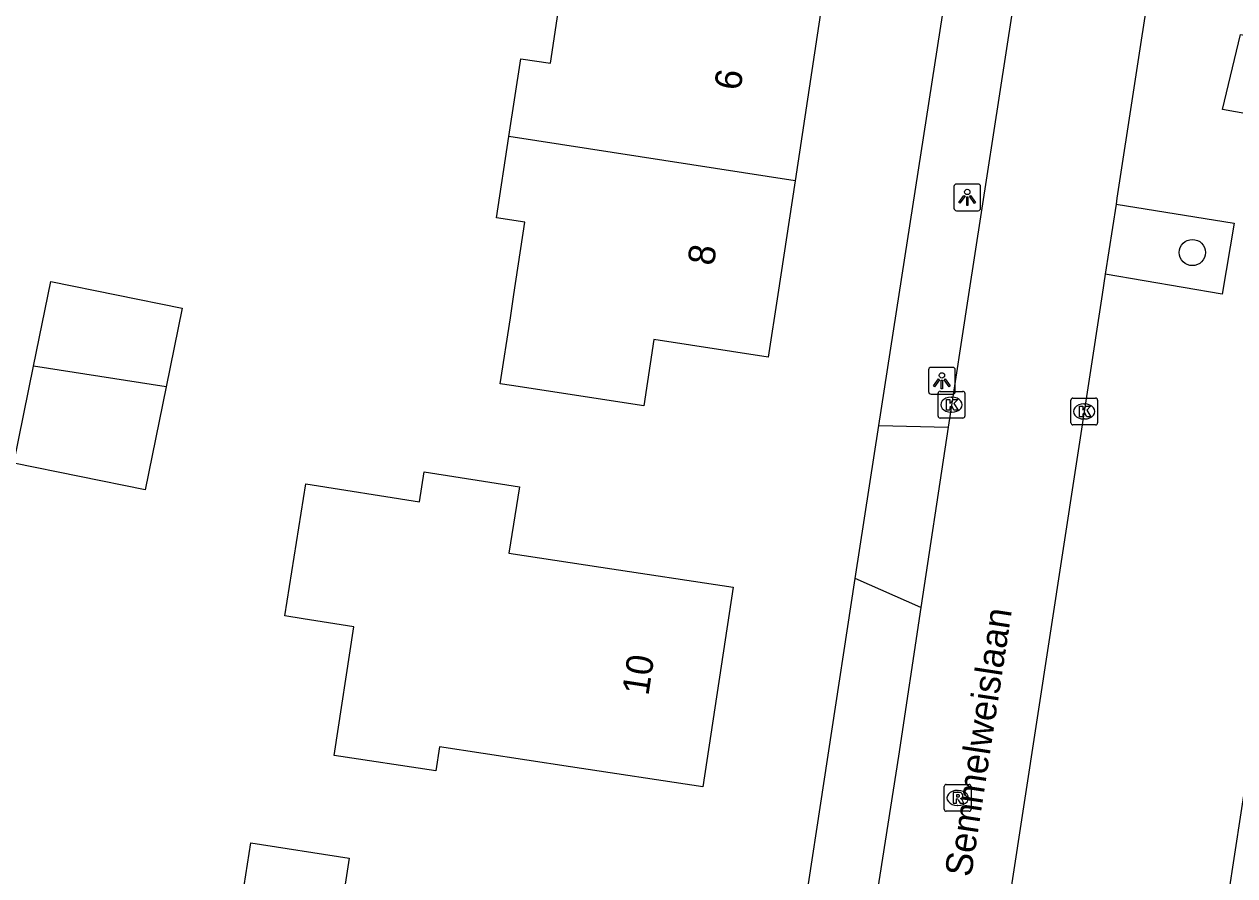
# Model space of a CAD drawing. Extents: x 161486 to 162249, y 379484 to 380829.
# Drawn here: x 161700.97 to 161746.18, y 380478.3 to 380510.09 of the extents above; entities that cross this region are included whole.
import ezdxf

# ---------------------------------------------------------------- set-up
doc = ezdxf.new("R2010")
doc.units = 0
for name, color, linetype in [('IMGEO_Boom', 7, 'Continuous'), ('IMGEO_Groenvoorziening', 7, 'Continuous'), ('IMGEO_Kolk', 7, 'Continuous'), ('IMGEO_Lichtpunt', 7, 'Continuous'), ('IMGEO_Openbare_ruimte_label', 7, 'Continuous'), ('IMGEO_Pand', 7, 'Continuous'), ('IMGEO_Pand_nummerreeks', 7, 'Continuous'), ('IMGEO_Rijbaan_lokaal_open', 7, 'Continuous'), ('IMGEO_Rioolput', 7, 'Continuous'), ('IMGEO_Voetpad_open', 7, 'Continuous')]:
    doc.layers.add(name, color=color, linetype=linetype)

msp = doc.modelspace()

# ---------------------------------------------------------------- linework, layer by layer
at = {"layer": 'IMGEO_Boom'}
msp.add_circle((161744.593, 380501.567), 0.489, dxfattribs=at)
at = {"layer": 'IMGEO_Groenvoorziening'}
for points in [[(161750.302, 380506.085), (161745.718, 380506.902), (161746.396, 380509.701), (161750.755, 380509.012)], [(161741.742, 380503.373), (161746.159, 380502.657), (161745.704, 380500.01), (161741.342, 380500.764)]]:
    msp.add_lwpolyline(points, dxfattribs=at)
at = {"layer": 'IMGEO_Kolk'}
for p, q in [((161735.097, 380495.458), (161735.097, 380496.31)), ((161735.172, 380496.384), (161736.024, 380496.384)), ((161735.585, 380496.164), (161735.61, 380496.164)), ((161736.098, 380496.31), (161736.098, 380495.458)), ((161740.055, 380495.206), (161740.055, 380496.058)), ((161740.13, 380496.132), (161740.982, 380496.132)), ((161741.056, 380496.058), (161741.056, 380495.206)), ((161735.608, 380495.604), (161735.583, 380495.604)), ((161740.543, 380495.912), (161740.568, 380495.912)), ((161736.024, 380495.384), (161735.172, 380495.384)), ((161740.982, 380495.132), (161740.13, 380495.132)), ((161740.566, 380495.352), (161740.541, 380495.352))]:
    msp.add_line(p, q, dxfattribs=at)
for points in [[(161735.097, 380495.458), (161735.097, 380496.31)], [(161735.172, 380496.384), (161736.024, 380496.384)], [(161735.418, 380496.084), (161735.541, 380496.084), (161735.541, 380495.933), (161735.671, 380496.084), (161735.835, 380496.084), (161735.689, 380495.933), (161735.842, 380495.684), (161735.69, 380495.684), (161735.605, 380495.848), (161735.541, 380495.781), (161735.541, 380495.684), (161735.418, 380495.684), (161735.418, 380496.084)], [(161736.098, 380496.31), (161736.098, 380495.458)], [(161740.055, 380495.206), (161740.055, 380496.058)], [(161740.13, 380496.132), (161740.982, 380496.132)], [(161741.056, 380496.058), (161741.056, 380495.206)], [(161740.376, 380495.832), (161740.499, 380495.832), (161740.499, 380495.681), (161740.629, 380495.832), (161740.793, 380495.832), (161740.647, 380495.681), (161740.8, 380495.432), (161740.648, 380495.432), (161740.563, 380495.596), (161740.499, 380495.529), (161740.499, 380495.432), (161740.376, 380495.432), (161740.376, 380495.832)], [(161736.024, 380495.384), (161735.172, 380495.384)], [(161740.982, 380495.132), (161740.13, 380495.132)]]:
    msp.add_lwpolyline(points, dxfattribs=at)
for centre, start, end in [((161735.174, 380496.308), 91.552, 178.448), ((161735.174, 380496.308), 91.552, 178.448), ((161736.022, 380496.308), 1.552, 88.448), ((161736.022, 380496.308), 1.552, 88.448), ((161740.132, 380496.056), 91.552, 178.448), ((161740.132, 380496.056), 91.552, 178.448), ((161740.98, 380496.056), 1.552, 88.448), ((161740.98, 380496.056), 1.552, 88.448), ((161735.174, 380495.46), 181.552, 268.448), ((161735.174, 380495.46), 181.552, 268.448), ((161736.022, 380495.46), 271.552, 358.448), ((161736.022, 380495.46), 271.552, 358.448), ((161740.132, 380495.208), 181.552, 268.448), ((161740.132, 380495.208), 181.552, 268.448), ((161740.98, 380495.208), 271.552, 358.448), ((161740.98, 380495.208), 271.552, 358.448)]:
    msp.add_arc(centre, 0.0765, start, end, dxfattribs=at)
for centre, major_axis, ratio, start_param, end_param in [((161735.584, 380495.884), (-0.387, 0.002), 0.722429, 4.712389, 7.853982), ((161735.609, 380495.884), (-0.39, 0.002), 0.717154, 1.570796, 4.712389), ((161740.542, 380495.632), (-0.387, 0.002), 0.722429, 4.712389, 7.853982), ((161740.567, 380495.632), (-0.39, 0.002), 0.717154, 1.570796, 4.712389)]:
    msp.add_ellipse(centre, major_axis=major_axis, ratio=ratio, start_param=start_param, end_param=end_param, dxfattribs=at)
at = {"layer": 'IMGEO_Lichtpunt'}
for p, q in [((161735.69, 380504.029), (161735.69, 380503.222)), ((161735.69, 380504.029), (161735.69, 380503.222)), ((161736.592, 380504.124), (161735.784, 380504.124)), ((161736.592, 380504.124), (161735.784, 380504.124)), ((161736.686, 380503.222), (161736.686, 380504.029)), ((161736.686, 380503.222), (161736.686, 380504.029)), ((161735.784, 380503.128), (161736.592, 380503.128)), ((161735.784, 380503.128), (161736.592, 380503.128)), ((161734.741, 380497.183), (161734.741, 380496.376)), ((161734.741, 380497.183), (161734.741, 380496.376)), ((161735.643, 380497.278), (161734.835, 380497.278)), ((161735.643, 380497.278), (161734.835, 380497.278)), ((161735.737, 380496.376), (161735.737, 380497.183)), ((161735.737, 380496.376), (161735.737, 380497.183)), ((161734.835, 380496.282), (161735.643, 380496.282)), ((161734.835, 380496.282), (161735.643, 380496.282))]:
    msp.add_line(p, q, dxfattribs=at)
for points in [[(161736.064, 380503.693), (161736.103, 380503.665), (161735.915, 380503.403), (161735.877, 380503.43), (161736.064, 380503.693)], [(161736.276, 380503.665), (161736.314, 380503.692), (161736.501, 380503.43), (161736.462, 380503.402), (161736.276, 380503.665)], [(161736.166, 380503.645), (161736.213, 380503.645), (161736.213, 380503.323), (161736.166, 380503.323), (161736.166, 380503.645)], [(161735.115, 380496.847), (161735.154, 380496.819), (161734.966, 380496.557), (161734.928, 380496.584), (161735.115, 380496.847)], [(161735.217, 380496.799), (161735.264, 380496.799), (161735.264, 380496.477), (161735.217, 380496.477), (161735.217, 380496.799)], [(161735.327, 380496.819), (161735.365, 380496.846), (161735.552, 380496.584), (161735.513, 380496.556), (161735.327, 380496.819)]]:
    msp.add_lwpolyline(points, dxfattribs=at)
for centre in [(161736.189, 380503.827), (161735.24, 380496.981)]:
    msp.add_circle(centre, 0.0994, dxfattribs=at)
for centre, start, end in [((161735.784, 380504.029), 90, 180), ((161735.784, 380504.029), 90, 180), ((161736.592, 380504.029), 0, 90), ((161736.592, 380504.029), 0, 90), ((161735.784, 380503.222), 180, 270), ((161735.784, 380503.222), 180, 270), ((161736.592, 380503.222), 270, 0), ((161736.592, 380503.222), 270, 360), ((161734.835, 380497.183), 90, 180), ((161734.835, 380497.183), 90, 180), ((161735.643, 380497.183), 0, 90), ((161735.643, 380497.183), 0, 90), ((161734.835, 380496.376), 180, 270), ((161734.835, 380496.376), 180, 270), ((161735.643, 380496.376), 270, 0), ((161735.643, 380496.376), 270, 360)]:
    msp.add_arc(centre, 0.0946, start, end, dxfattribs=at)
at = {"layer": 'IMGEO_Pand'}
for points in [[(161719.071, 380505.897), (161719.513, 380508.8), (161720.621, 380508.632), (161721.165, 380512.209), (161725.803, 380511.503), (161730.746, 380510.751), (161729.756, 380504.244)], [(161729.756, 380504.244), (161729.11, 380500), (161728.754, 380497.661), (161724.484, 380498.313), (161724.107, 380495.842), (161719.165, 380496.596), (161718.74, 380496.661), (161719.125, 380499.13), (161719.257, 380500), (161719.669, 380502.705), (161718.61, 380502.865), (161719.071, 380505.897)], [(161729.756, 380504.244), (161719.071, 380505.897)], [(161701.319, 380497.322), (161701.964, 380500.487), (161706.873, 380499.487), (161706.276, 380496.554)], [(161706.276, 380496.554), (161705.493, 380492.704), (161700.583, 380493.703), (161701.319, 380497.322)], [(161706.276, 380496.554), (161701.319, 380497.322)], [(161711.483, 380492.936), (161715.731, 380492.264), (161715.908, 380493.378), (161719.464, 380492.816), (161719.073, 380490.346), (161722.506, 380489.822), (161727.448, 380489.068), (161726.311, 380481.615), (161721.369, 380482.369), (161716.481, 380483.114), (161716.343, 380482.215), (161712.547, 380482.794), (161713.279, 380487.589), (161711.392, 380487.887), (161710.701, 380487.997), (161711.483, 380492.936)], [(161709.429, 380479.53), (161713.108, 380478.958), (161712.179, 380472.983), (161708.5, 380473.555), (161709.429, 380479.53)]]:
    msp.add_lwpolyline(points, dxfattribs=at)
at = {"layer": 'IMGEO_Rijbaan_lokaal_open'}
for points in [[(161743.247, 380513.169), (161743.044, 380511.848), (161741.775, 380503.591), (161741.742, 380503.373)], [(161737.863, 380510.556), (161736.234, 380500), (161735.469, 380495.044)], [(161744.753, 380469.744), (161744.957, 380471.08), (161745.711, 380476.014), (161746.655, 380482.196), (161749.364, 380500), (161749.564, 380501.311), (161750.302, 380506.085)], [(161741.742, 380503.373), (161741.342, 380500.764)], [(161741.342, 380500.764), (161741.225, 380500), (161737.808, 380477.707), (161737.621, 380476.484)], [(161735.469, 380495.044), (161735.406, 380494.637), (161734.457, 380488.318)], [(161734.457, 380488.318), (161733.623, 380482.759), (161732.522, 380475.779)]]:
    msp.add_lwpolyline(points, dxfattribs=at)
at = {"layer": 'IMGEO_Rioolput'}
for p, q in [((161735.33, 380480.78), (161735.33, 380481.632)), ((161735.405, 380481.706), (161736.257, 380481.706)), ((161736.331, 380481.632), (161736.331, 380480.78)), ((161735.818, 380481.486), (161735.843, 380481.486)), ((161736.257, 380480.706), (161735.405, 380480.706)), ((161735.841, 380480.926), (161735.816, 380480.926))]:
    msp.add_line(p, q, dxfattribs=at)
for points in [[(161735.33, 380480.78), (161735.33, 380481.632)], [(161735.405, 380481.706), (161736.257, 380481.706)], [(161736.331, 380481.632), (161736.331, 380480.78)], [(161735.919, 380481.404), (161735.667, 380481.406), (161735.667, 380481.006)], [(161735.667, 380481.006), (161735.791, 380481.006), (161735.791, 380481.168), (161735.802, 380481.168)], [(161735.845, 380481.325), (161735.791, 380481.325), (161735.791, 380481.244)], [(161735.791, 380481.244), (161735.843, 380481.244)], [(161735.849, 380481.139), (161735.92, 380481.006), (161736.06, 380481.006), (161735.995, 380481.132)], [(161736.257, 380480.706), (161735.405, 380480.706)]]:
    msp.add_lwpolyline(points, dxfattribs=at)
for centre, radius, start, end in [((161735.407, 380481.63), 0.0765, 91.552, 178.448), ((161735.407, 380481.63), 0.0765, 91.552, 178.448), ((161736.255, 380481.63), 0.0765, 1.552, 88.448), ((161736.255, 380481.63), 0.0765, 1.552, 88.448), ((161735.801, 380481.115), 0.0533, 26.0293, 88.6989), ((161735.827, 380481.433), 0.19, 274.7715, 282.9687), ((161735.851, 380481.229), 0.0964, 77.0061, 93.1865), ((161735.865, 380481.286), 0.0378, 276.6634, 79.6772), ((161735.918, 380481.294), 0.109, 350.3612, 89.416), ((161735.916, 380481.294), 0.112, 277.5842, 350.9817), ((161735.9, 380481.079), 0.108, 29.5134, 73.7905), ((161735.407, 380480.782), 0.0765, 181.552, 268.448), ((161735.407, 380480.782), 0.0765, 181.552, 268.448), ((161736.255, 380480.782), 0.0765, 271.552, 358.448), ((161736.255, 380480.782), 0.0765, 271.552, 358.448)]:
    msp.add_arc(centre, radius, start, end, dxfattribs=at)
for centre, major_axis, ratio, start_param, end_param in [((161735.817, 380481.206), (-0.387, 0.002), 0.722429, 4.712389, 7.853982), ((161735.842, 380481.206), (-0.39, 0.002), 0.717154, 1.570796, 4.712389)]:
    msp.add_ellipse(centre, major_axis=major_axis, ratio=ratio, start_param=start_param, end_param=end_param, dxfattribs=at)
at = {"layer": 'IMGEO_Voetpad_open'}
for points in [[(161732.879, 380495.109), (161733.64, 380500), (161735.486, 380511.867)], [(161732.005, 380489.393), (161732.879, 380495.109)], [(161732.879, 380495.109), (161735.469, 380495.044)], [(161729.989, 380476.206), (161732.005, 380489.393)], [(161734.457, 380488.318), (161732.005, 380489.393)]]:
    msp.add_lwpolyline(points, dxfattribs=at)

# ---------------------------------------------------------------- texts
at = {"layer": 'IMGEO_Openbare_ruimte_label'}
msp.add_text('Semmelweislaan', height=1, rotation=81.3105, dxfattribs=at).set_placement((161736.329, 380478.222))
at = {"layer": 'IMGEO_Pand_nummerreeks'}
for s, rotation, p in [('6', 81.3473, (161727.715, 380507.586)), ('8', 81.3473, (161726.72, 380501.045)), ('10', 81.3261, (161724.278, 380484.997))]:
    msp.add_text(s, height=1, rotation=rotation, dxfattribs=at).set_placement(p)

doc.saveas('drawing.dxf')
